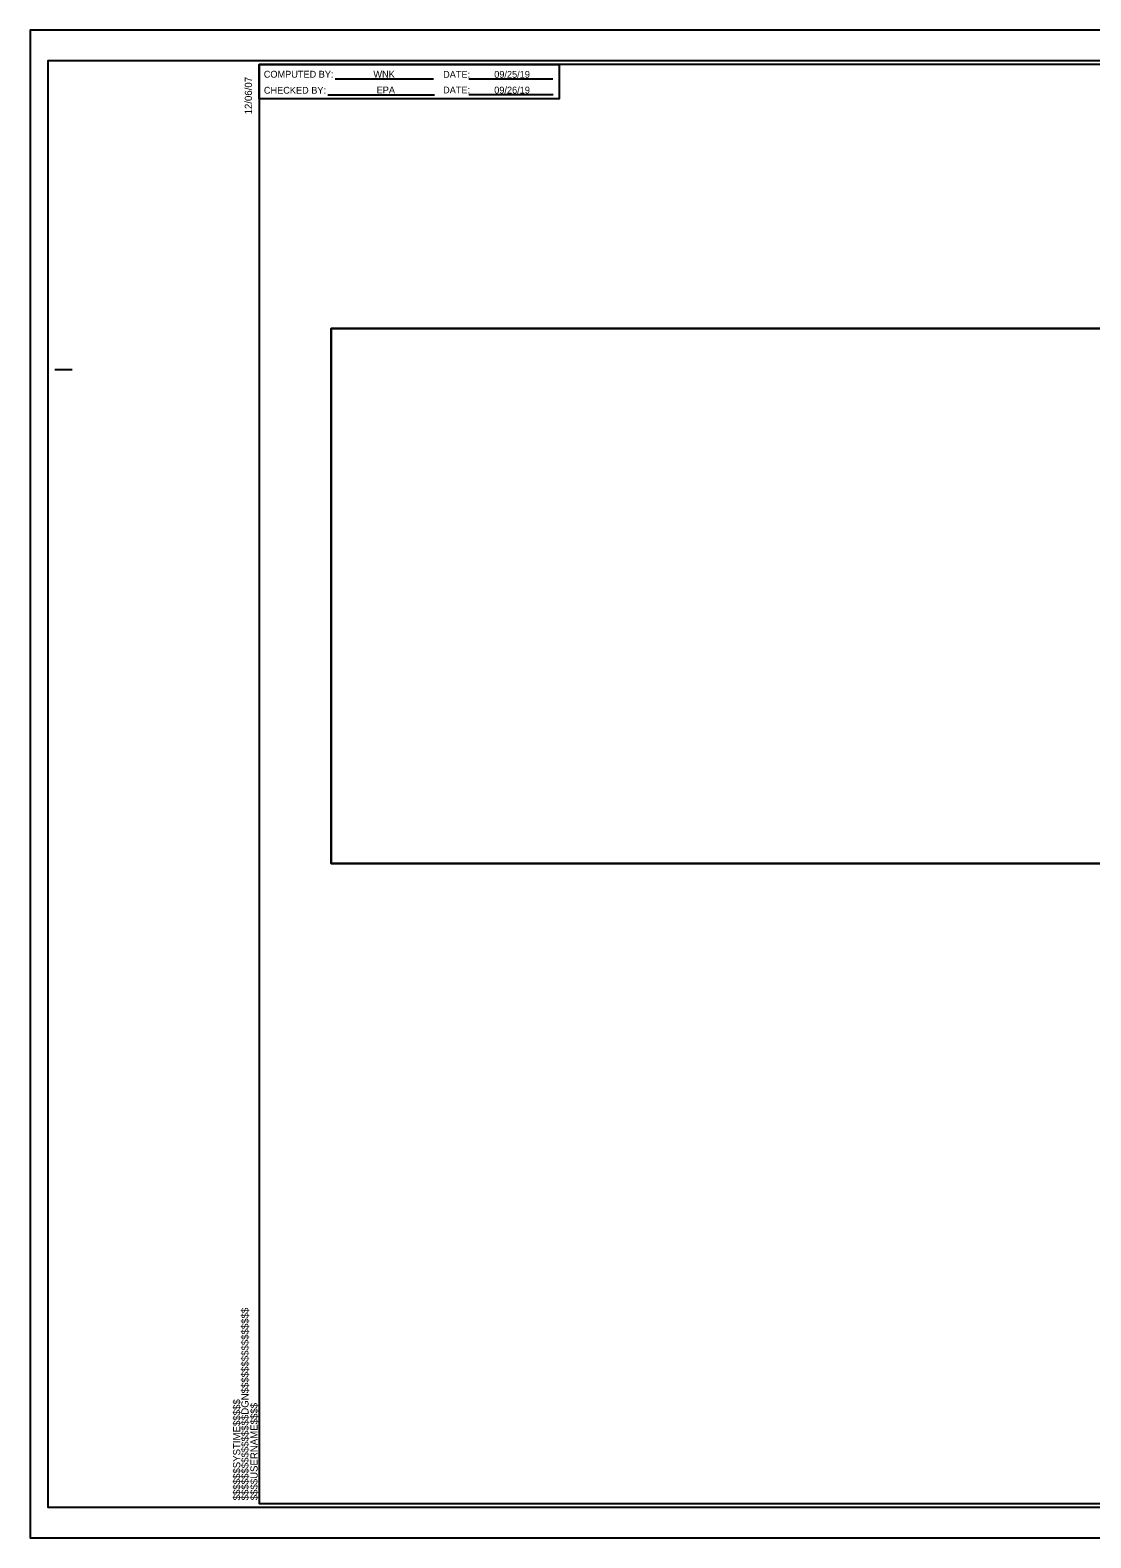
# Model space of a CAD drawing. Extents: x 1298931 to 1298964.7, y 1260142.8 to 1260164.8.
# Drawn here: x 1298930.99 to 1298946.47, y 1260142.76 to 1260164.76 of the extents above; entities that cross this region are included whole.
import ezdxf

# ---------------------------------------------------------------- set-up
doc = ezdxf.new("R2010")
doc.units = 0
for name, color, linetype in [('Default', 7, 'Continuous'), ('Sheet Cutting Line CELL', 7, 'Continuous'), ('Sheet Data Field CELL', 7, 'Continuous'), ('Sheet Plot Border Inside CELL', 7, 'Continuous'), ('Sheet Plot Border Outside CELL', 7, 'Continuous'), ('Sheet Summary Combination CELL', 7, 'Continuous')]:
    doc.layers.add(name, color=color, linetype=linetype)

msp = doc.modelspace()

# ---------------------------------------------------------------- linework, layer by layer
at = {"layer": 'Default'}
for points in [[(1298935.382, 1260160.41), (1298963.251, 1260160.41), (1298963.251, 1260152.604), (1298935.382, 1260152.604)], [(1298935.382, 1260152.604), (1298963.251, 1260152.604), (1298963.251, 1260160.41), (1298935.382, 1260160.41)]]:
    msp.add_lwpolyline(points, close=True, dxfattribs=at)
at = {"layer": 'Sheet Cutting Line CELL'}
for p, q in [((1298964.671, 1260164.764), (1298930.991, 1260164.764)), ((1298930.991, 1260164.764), (1298930.991, 1260142.764)), ((1298930.991, 1260142.764), (1298964.671, 1260142.764))]:
    msp.add_line(p, q, dxfattribs=at)
at = {"layer": 'Sheet Plot Border Inside CELL'}
msp.add_lwpolyline([(1298964.581, 1260164.315), (1298931.251, 1260164.315), (1298931.251, 1260143.213), (1298964.581, 1260143.213)], close=True, dxfattribs=at)
at = {"layer": 'Sheet Plot Border Outside CELL'}
msp.add_lwpolyline([(1298964.671, 1260164.764), (1298930.991, 1260164.764), (1298930.991, 1260142.764), (1298964.671, 1260142.764)], close=True, dxfattribs=at)
at = {"layer": 'Sheet Summary Combination CELL'}
for p, q in [((1298935.444, 1260164.056), (1298936.875, 1260164.056)), ((1298937.391, 1260164.053), (1298938.619, 1260164.053)), ((1298935.335, 1260163.822), (1298936.889, 1260163.822)), ((1298937.394, 1260163.823), (1298938.622, 1260163.823)), ((1298931.353, 1260159.814), (1298931.603, 1260159.814)), ((1298934.331, 1260143.264), (1298934.331, 1260143.264))]:
    msp.add_line(p, q, dxfattribs=at)
for points in [[(1298964.331, 1260164.264), (1298934.331, 1260164.264), (1298934.331, 1260143.264), (1298964.331, 1260143.264)], [(1298934.331, 1260164.264), (1298938.711, 1260164.264), (1298938.711, 1260163.764), (1298934.331, 1260163.764)]]:
    msp.add_lwpolyline(points, close=True, dxfattribs=at)

# ---------------------------------------------------------------- texts
at = {"layer": 'Sheet Data Field CELL'}
for s, p in [('WNK', (1298936, 1260164.071)), ('09/25/19', (1298937.763, 1260164.069)), ('EPA', (1298936.047, 1260163.841)), ('09/26/19', (1298937.763, 1260163.839))]:
    msp.add_text(s, height=0.1, dxfattribs=at).set_placement(p)
at = {"layer": 'Sheet Summary Combination CELL'}
for s, p in [('12/06/07', (1298934.228, 1260163.535)), ('$$$$$$$$$$$$$$$$DGN$$$$$$$$$$$$$$$$', (1298934.178, 1260143.311)), ('$$$$$$SYSTIME$$$$$', (1298934.057, 1260143.311)), ('$$$$USERNAME$$$$', (1298934.31, 1260143.312))]:
    msp.add_text(s, height=0.105, rotation=90, dxfattribs=at).set_placement(p)
for s, p in [('COMPUTED BY:', (1298934.4, 1260164.071)), ('DATE:', (1298937.017, 1260164.069)), ('CHECKED BY:', (1298934.402, 1260163.837)), ('DATE:', (1298937.017, 1260163.841))]:
    msp.add_text(s, height=0.1, dxfattribs=at).set_placement(p)

doc.saveas('drawing.dxf')
